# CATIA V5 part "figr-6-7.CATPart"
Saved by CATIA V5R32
Part number: Part1
Bounding box of the stored display mesh (mm): x -62.5 to 62.5, y -75 to 75, z 0 to 20
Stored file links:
  D:\PROJECTS\Project 2022\CATIA V5 6R 2022\Resources\Part Files\c06_catia_v5_6r2022_prt\figr-6-7.CATPart
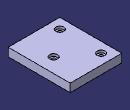
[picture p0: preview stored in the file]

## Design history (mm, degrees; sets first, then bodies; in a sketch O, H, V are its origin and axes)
Body1 (main body)
  Sketch1 on xy-plane, origin (0, 0, 0), H (1, 0, 0), V (0, 1, 0)
    line L1 (-62.5, 75) -> (62.5, 75)
    line L2 (62.5, 75) -> (62.5, -75)
    line L3 (62.5, -75) -> (-62.5, -75)
    line L4 (-62.5, -75) -> (-62.5, 75)
    axis line L5 (62.5, -75) -> (-62.5, 75)
    length L2 = 150
    length L3 = 125
    horizontal: L1 H, L3 H
    vertical: L2 V, L4 V
    midpoint: O L5
  Pad1: profile Sketch1, direction (0, 0, 1), length 20
  Sketch2 on face of Pad1, origin (-40.5285, -55.3052, 20), H (1, 0, 0), V (0, 1, 0)
    point P1 (3.0285, 5.3052)
    reference projected line E1 (-21.9715, -19.6948) -> (103.0285, -19.6948) from edge [face of Pad1 | face of Pad1]
    reference projected line E2 (-21.9715, 130.3052) -> (-21.9715, -19.6948) from edge [face of Pad1 | face of Pad1]
    distance P1 E1 = 25
    distance P1 E2 = 25
  Hole1: placed by Sketch2, at (-37.5, -50, 20) direction (0, 0, -1), diameter 11, through (limit type 3), counterbore diameter 19, counterbore depth 6
  Sketch3 on face of Pad1, origin (-46.6283, 59.6815, 20), H (1, 0, 0), V (0, 1, 0)
    point P1 (9.1283, -9.6815)
    reference projected line E1 (-15.8717, 15.3185) -> (-15.8717, -134.6815) from edge [face of Pad1 | face of Pad1]
    reference projected line E2 (109.1283, 15.3185) -> (-15.8717, 15.3185) from edge [face of Pad1 | face of Pad1]
    distance P1 E1 = 25
    distance P1 E2 = 25
  Hole2: placed by Sketch3, at (-37.5, 50, 20) direction (0, 0, -1), diameter 11, through (limit type 3), counterbore diameter 19, counterbore depth 6
  Sketch4 on face of Pad1, origin (29.7716, -8.2192, 20), H (1, 0, 0), V (0, 1, 0)
    point P1 (-2.2716, 8.2192)
    reference projected line E1 (-92.2716, -66.7808) -> (32.7284, -66.7808) from edge [face of Pad1 | face of Pad1]
    reference projected line E2 (32.7284, -66.7808) -> (32.7284, 83.2192) from edge [face of Pad1 | face of Pad1]
    distance P1 E1 = 75
    distance P1 E2 = 35
  Hole3: placed by Sketch4, at (27.5, 0, 20) direction (0, 0, -1), diameter 11, through (limit type 3), counterbore diameter 19, counterbore depth 6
